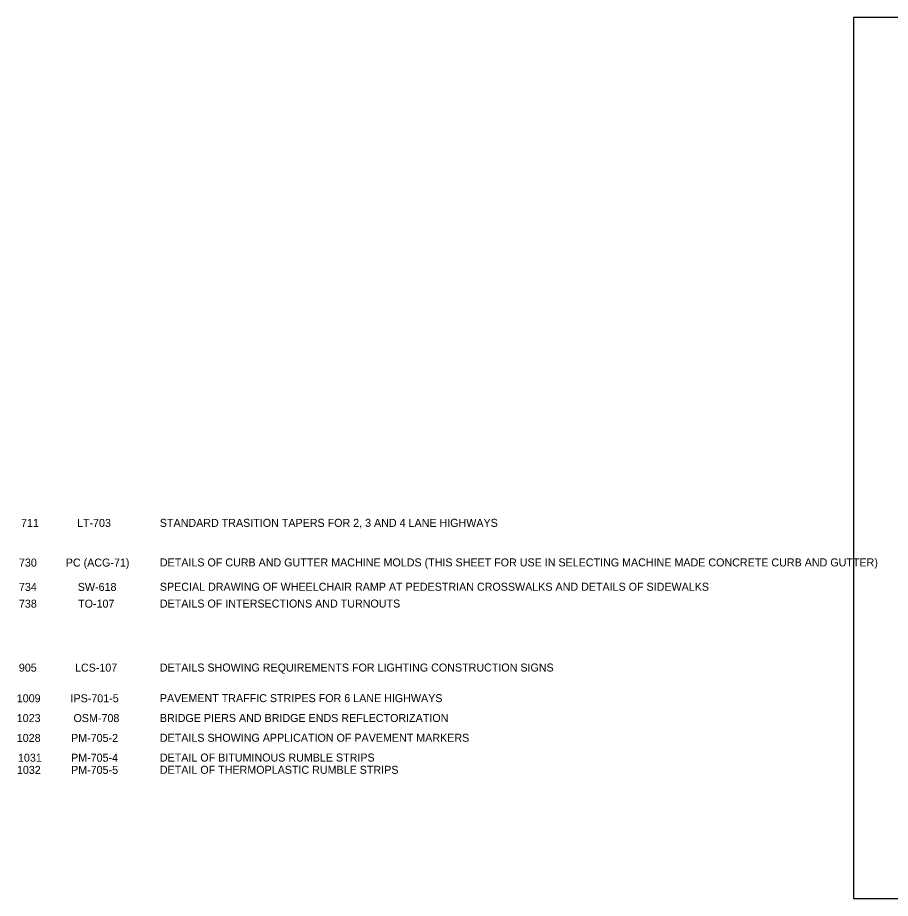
# Model space of a CAD drawing. Extents: x -12822 to 16384, y -6351 to 1913.
# Drawn here: x -1894 to -804, y -3350 to -2250 of the extents above; entities that cross this region are included whole.
import ezdxf

# ---------------------------------------------------------------- set-up
doc = ezdxf.new("R2010")
doc.units = 0
doc.layers.add('Level 10', color=7, linetype='Continuous')
doc.layers.add('Level 62', color=7, linetype='Continuous')

msp = doc.modelspace()

# ---------------------------------------------------------------- linework, layer by layer
at = {"layer": 'Level 62'}
msp.add_lwpolyline([(-850, -3349.9), (850, -3349.9), (850, -2249.9), (-850, -2249.9)], close=True, dxfattribs=at)

# ---------------------------------------------------------------- texts
at = {"layer": 'Level 10'}
for s, p in [('711', (-1889.7, -2886)), ('LT-703', (-1819.8, -2886)), ('STANDARD TRASITION TAPERS FOR 2, 3 AND 4 LANE HIGHWAYS', (-1716.3, -2885.9)), ('730', (-1892.3, -2935.5)), ('PC (ACG-71)', (-1833.8, -2935.5)), ('DETAILS OF CURB AND GUTTER MACHINE MOLDS (THIS SHEET FOR USE IN SELECTING MACHINE MADE CONCRETE CURB AND GUTTER)', (-1716.3, -2935.3)), ('734', (-1892.3, -2965.9)), ('SW-618', (-1818.8, -2965.9)), ('SPECIAL DRAWING OF WHEELCHAIR RAMP AT PEDESTRIAN CROSSWALKS AND DETAILS OF SIDEWALKS', (-1716.3, -2965.7)), ('738', (-1892.3, -2986.8)), ('TO-107', (-1818.4, -2986.8)), ('DETAILS OF INTERSECTIONS AND TURNOUTS', (-1716.3, -2986.7)), ('905', (-1892.4, -3066.7)), ('LCS-107', (-1822.3, -3066.7)), ('DETAILS SHOWING REQUIREMENTS FOR LIGHTING CONSTRUCTION SIGNS', (-1716.3, -3066.6)), ('1009', (-1895, -3105)), ('IPS-701-5', (-1827.9, -3105)), ('PAVEMENT TRAFFIC STRIPES FOR 6 LANE HIGHWAYS', (-1716.3, -3104.8)), ('1023', (-1895, -3129.7)), ('OSM-708', (-1824.1, -3129.7)), ('BRIDGE PIERS AND BRIDGE ENDS REFLECTORIZATION', (-1716.3, -3129.6)), ('1028', (-1895, -3154.5)), ('PM-705-2', (-1827.2, -3154.5)), ('DETAILS SHOWING APPLICATION OF PAVEMENT MARKERS', (-1716.3, -3154.3)), ('1031', (-1893.5, -3179.2)), ('PM-705-4', (-1827.2, -3179.2)), ('DETAIL OF BITUMINOUS RUMBLE STRIPS', (-1716.3, -3179)), ('1032', (-1894.8, -3194.4)), ('PM-705-5', (-1827.2, -3194.4)), ('DETAIL OF THERMOPLASTIC RUMBLE STRIPS', (-1716.3, -3194.3))]:
    msp.add_text(s, height=10, dxfattribs=at).set_placement(p)

doc.saveas('drawing.dxf')
